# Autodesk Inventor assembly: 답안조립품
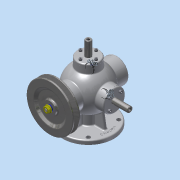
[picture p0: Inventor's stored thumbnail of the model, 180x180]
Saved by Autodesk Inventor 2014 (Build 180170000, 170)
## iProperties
Created: 2016-01
Part Number: 답안조립품
Document SubType Name: Assembly
Designer: Administrator
Author: Administrator
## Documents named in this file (17)
- C:\Users\Administrator\Desktop\360108V1015\답안조립품.iam
- C:\Users\Administrator\Desktop\360108V1015\본체.ipt
- C:\Users\Administrator\Desktop\360108V1015\15-스프링.ipt
- C:\Users\Administrator\Desktop\360108V1015\16-스프링.ipt
- C:\Users\Administrator\Desktop\360108V1015\V-벨트풀리.ipt
- C:\Users\Administrator\Desktop\360108V1015\너트-M8x1.ipt
- C:\Users\Administrator\Desktop\360108V1015\뒤커버.ipt
- C:\Users\Administrator\Desktop\360108V1015\베어링- 6202.ipt
- C:\Users\Administrator\Desktop\360108V1015\본체커버.ipt
- C:\Users\Administrator\Desktop\360108V1015\볼트 M4x0.7.ipt
- C:\Users\Administrator\Desktop\360108V1015\슬라이드 커버.ipt
- C:\Users\Administrator\Desktop\360108V1015\슬라이드.ipt
- C:\Users\Administrator\Desktop\360108V1015\앞커버.ipt
- C:\Users\Administrator\Desktop\360108V1015\오일실.ipt
- C:\Users\Administrator\Desktop\360108V1015\와셔 8x17.ipt
- C:\Users\Administrator\Desktop\360108V1015\축.ipt
- C:\Users\Administrator\Desktop\360108V1015\키-4x4.ipt
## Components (20 placed, 4 different names)
1. 15-스프링:1
2. 16-스프링:1
3. V-벨트풀리:1 — 플러쉬:1, 플러쉬:2, 각도:2, 각도:3
4. M4x0.7x12:3
5. M4x0.7x12:4
6. M4x0.7x12:5
7. M4x0.7x12:6
8. M4x0.7x12:7
9. M4x0.7x12:8
10. M4x0.7x12:9
11. M4x0.7x12:10
12. M4x0.7x12:11
13. M4x0.7x12:1
14. M4x0.7x12:12
15. M4x0.7x12:13
16. M4x0.7x12:14
17. M4x0.7x12:2
18. M4x0.7x12:15
19. M4x0.7x12:16
20. M4x0.7x12:17
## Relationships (4: Flush 2, Angle 2)
- 플러쉬:1 [Flush]: V-벨트풀리:1
- 플러쉬:2 [Flush]: V-벨트풀리:1
- 각도:2 [Angle]: V-벨트풀리:1
- 각도:3 [Angle]: V-벨트풀리:1
